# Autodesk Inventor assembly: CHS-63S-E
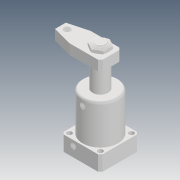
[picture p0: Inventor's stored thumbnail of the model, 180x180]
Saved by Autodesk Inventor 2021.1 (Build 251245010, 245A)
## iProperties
Created: 2019-05
Part Number: CHS-63S-E
Description: STEP AP203
Document SubType Name: Assembly
Designer: user
Title: chs-63s-e_asm.STEP
Revision Number: ÈÎºÎ
Sending System: SolidWorks 2017
Preprocessor: SwSTEP 2.0
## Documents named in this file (5)
- D:\Vault_2016\Projekty\Clamptek\Hydraulic\CHS\CHS-63\Inventor\CHS-63S-E\CHS-63S-E.iam
- D:\Vault_2016\Projekty\Clamptek\Hydraulic\CHS\CHS-63\Inventor\CHS-63S-E\CHS-63-03-E_1.ipt
- D:\Vault_2016\Projekty\Clamptek\Hydraulic\CHS\CHS-63\Inventor\CHS-63S-E\CHS-63S-02-E.ipt
- D:\Vault_2016\Projekty\Clamptek\Hydraulic\CHS\CHS-63\Inventor\CHS-63S-E\CHS-63S-01_3.ipt
- D:\Vault_2016\Projekty\Clamptek\Hydraulic\CHS\CHS-63\Inventor\CHS-63S-E\M24_3.ipt
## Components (4 placed, 4 different names)
1. CHS-63-03-E_1_1
2. CHS-63S-02-E_2
3. CHS-63S-01_3_3
4. M24_3_4
